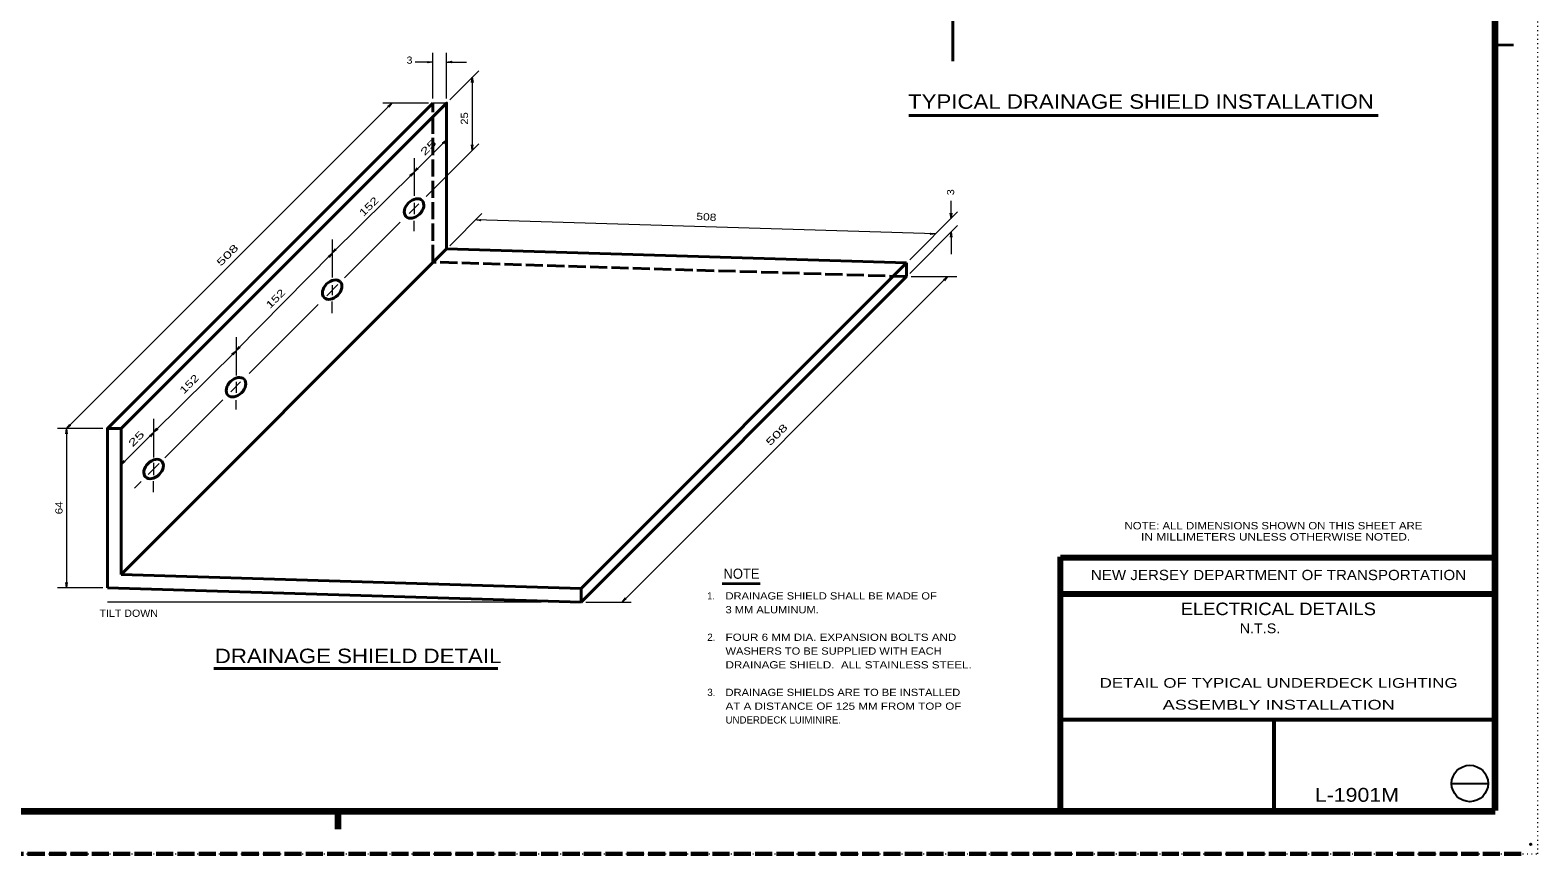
# Model space of a CAD drawing. Extents: x 312583 to 312854, y 144419 to 144597.
# Drawn here: x 312695 to 312853.5, y 144418.6 to 144505.2 of the extents above; entities that cross this region are included whole.
import ezdxf
from ezdxf.enums import TextEntityAlignment as Align

# ---------------------------------------------------------------- set-up
doc = ezdxf.new("R2010")
doc.units = 0
doc.header["$LTSCALE"] = 0.3
doc.header["$PDMODE"] = 32
doc.header["$PDSIZE"] = 0.15
doc.linetypes.add('DOTTED', pattern=[1.5, 0.3, -1.2])
doc.linetypes.add('LONG_DASHED', pattern=[7.5, 6, -1.5])
for name, color, linetype, lineweight in [('1', 7, 'Continuous', 40), ('10', 7, 'Continuous', 25), ('2', 7, 'Continuous', 13), ('62', 7, 'DOTTED', 13), ('63', 7, 'LONG_DASHED', 60)]:
    doc.layers.add(name, color=color, linetype=linetype, lineweight=lineweight)
doc.layers.add('39', color=7, linetype='Continuous')
doc.layers.add('5', color=7, linetype='Continuous')

msp = doc.modelspace()

# ---------------------------------------------------------------- linework, layer by layer
at = {"layer": '1', "lineweight": 158}
for p, q in [((312849, 144423.1446), (312849, 144585.0846)), ((312616.5, 144423.0846), (312849, 144423.0846)), ((312727.35, 144421.1646), (312727.35, 144423.0846))]:
    msp.add_line(p, q, dxfattribs=at)
at = {"layer": '1', "lineweight": 35}
msp.add_line((312849, 144503.6216), (312850.932, 144503.6216), dxfattribs=at)
at = {"layer": '1', "lineweight": 80}
for p, q in [((312803.31, 144423.1446), (312803.31, 144449.8146)), ((312803.31, 144449.7246), (312849, 144449.7246)), ((312803.31, 144445.9146), (312849, 144445.9146))]:
    msp.add_line(p, q, dxfattribs=at)
at = {"layer": '1', "lineweight": 53}
for p, q in [((312849, 144432.6666), (312803.092, 144432.6666)), ((312825.7547, 144432.6666), (312825.7547, 144423.1446))]:
    msp.add_line(p, q, dxfattribs=at)
at = {"layer": '10'}
msp.add_line((312844.4384, 144425.9659), (312848.2794, 144425.9659), dxfattribs=at)
msp.add_circle((312846.3494, 144425.9805), 1.9159, dxfattribs=at)
at = {"layer": '2', "lineweight": 40}
for p, q in [((312791.9754, 144501.9119), (312791.9754, 144578.5786)), ((312787.3711, 144496.1849), (312836.6956, 144496.1849)), ((312704.5283, 144447.9463), (312738.7523, 144482.1703)), ((312787.1213, 144480.6983), (312738.7523, 144482.1703)), ((312752.8973, 144446.4743), (312787.1213, 144480.6983)), ((312787.1213, 144480.6983), (312787.1213, 144479.2646)), ((312752.8973, 144445.0406), (312787.1213, 144479.2646)), ((312704.5283, 144463.2796), (312703.0946, 144463.2796)), ((312704.5283, 144447.9463), (312704.5283, 144463.2796)), ((312752.8973, 144445.0406), (312703.0946, 144446.5586)), ((312714.2947, 144438.0563), (312744.1415, 144438.0563))]:
    msp.add_line(p, q, dxfattribs=at)
at = {"layer": '2'}
for p, q in [((312737.3186, 144497.9789), (312737.3186, 144502.7706)), ((312738.7523, 144497.9789), (312738.7523, 144502.7706)), ((312737.3186, 144501.8123), (312735.4581, 144501.8123)), ((312738.7523, 144501.8123), (312740.853, 144501.8123)), ((312739.0896, 144497.8409), (312742.1333, 144500.8846)), ((312741.4586, 144500.2099), (312741.4586, 144492.5432)), ((312698.786, 144463.2796), (312733.01, 144497.5036)), ((312736.8433, 144497.5036), (312732.0516, 144497.5036)), ((312738.7523, 144497.5036), (312737.3186, 144497.5036)), ((312738.7523, 144493.6473), (312735.333, 144490.2512)), ((312742.1333, 144493.2179), (312736.5903, 144487.6749)), ((312735.333, 144491.6923), (312735.333, 144487.7439)), ((312735.333, 144490.2509), (312726.7233, 144481.7339)), ((312734.8116, 144485.8809), (312735.8313, 144486.9159)), ((312735.333, 144487.0233), (312735.333, 144485.8273)), ((312791.798, 144485.3749), (312791.798, 144487.2389)), ((312728.0343, 144479.1189), (312733.884, 144484.9686)), ((312735.333, 144484.0333), (312735.333, 144485.1066)), ((312739.0896, 144482.5076), (312742.4706, 144485.8886)), ((312790.165, 144483.7419), (312741.796, 144485.2139)), ((312787.4586, 144481.0356), (312792.4726, 144486.0496)), ((312787.4586, 144479.6019), (312792.4726, 144484.6159)), ((312726.7233, 144483.1669), (312726.7233, 144479.1726)), ((312791.798, 144483.9413), (312791.798, 144481.6336)), ((312726.7233, 144481.7256), (312716.611, 144471.4781)), ((312726.1713, 144477.2483), (312727.329, 144478.4213)), ((312726.7233, 144478.3599), (312726.7233, 144477.3173)), ((312757.2136, 144445.0406), (312791.4376, 144479.2646)), ((312787.6043, 144479.2646), (312792.396, 144479.2646)), ((312726.7233, 144475.4083), (312726.7233, 144476.6579)), ((312718.0063, 144469.0909), (312725.259, 144476.3436)), ((312716.611, 144472.9089), (312716.611, 144468.8686)), ((312716.611, 144471.4676), (312707.9476, 144462.874)), ((312716.0743, 144467.1436), (312717.1016, 144468.1863)), ((312716.611, 144468.1939), (312716.611, 144467.0286)), ((312709.1206, 144460.1976), (312715.231, 144466.3156)), ((312716.611, 144465.2729), (312716.611, 144466.2619)), ((312707.9476, 144464.3069), (312707.9476, 144460.2436)), ((312702.6193, 144463.2796), (312697.8276, 144463.2796)), ((312698.786, 144463.2796), (312698.786, 144446.5586)), ((312707.9476, 144462.8656), (312704.5283, 144459.4692)), ((312707.388, 144458.4726), (312708.5303, 144459.6073)), ((312707.9476, 144459.6839), (312707.9476, 144458.3729)), ((312705.939, 144457.0159), (312706.6443, 144457.7213)), ((312707.9476, 144456.5866), (312707.9476, 144457.7443)), ((312702.6193, 144446.5586), (312697.8276, 144446.5586)), ((312748.696, 144445.0406), (312703.0946, 144445.0406)), ((312753.3803, 144445.0406), (312758.172, 144445.0406))]:
    msp.add_line(p, q, dxfattribs=at)
at = {"layer": '2', "linetype": 'LONG_DASHED', "lineweight": 40}
for p, q in [((312737.3186, 144480.7826), (312737.3186, 144497.5036)), ((312787.1213, 144479.2646), (312737.3186, 144480.7826))]:
    msp.add_line(p, q, dxfattribs=at)
at = {"layer": '2', "lineweight": 35}
msp.add_line((312767.7342, 144446.9907), (312771.7367, 144446.9907), dxfattribs=at)
at = {"layer": '2'}
for points in [[(312736.7666, 144501.8813), (312737.3186, 144501.8123), (312736.7666, 144501.7356), (312736.8203, 144501.8123)], [(312739.3043, 144501.7433), (312738.7523, 144501.8123), (312739.3043, 144501.8889), (312739.2506, 144501.8123)], [(312741.3896, 144499.6579), (312741.4586, 144500.2099), (312741.5353, 144499.6579), (312741.4586, 144499.7116)], [(312732.573, 144497.1586), (312733.01, 144497.5036), (312732.6726, 144497.0589), (312732.6573, 144497.1509)], [(312738.3153, 144493.3099), (312738.7523, 144493.6473), (312738.415, 144493.2026), (312738.3996, 144493.2946)], [(312741.5276, 144493.0953), (312741.4586, 144492.5433), (312741.382, 144493.0953), (312741.4586, 144493.0416)], [(312734.896, 144489.9136), (312735.333, 144490.2509), (312734.9956, 144489.8063), (312734.9803, 144489.8983)], [(312735.77, 144490.5883), (312735.333, 144490.2509), (312735.6703, 144490.6956), (312735.6856, 144490.6036)], [(312742.348, 144485.1296), (312741.796, 144485.2139), (312742.348, 144485.2753), (312742.2943, 144485.1986)], [(312791.867, 144485.9269), (312791.798, 144485.3749), (312791.7213, 144485.9269), (312791.798, 144485.8733)], [(312789.613, 144483.8263), (312790.165, 144483.7419), (312789.613, 144483.6806), (312789.6666, 144483.7573)], [(312791.729, 144483.3893), (312791.798, 144483.9413), (312791.8746, 144483.3893), (312791.798, 144483.4429)], [(312726.2863, 144481.3806), (312726.7233, 144481.7256), (312726.3936, 144481.2809), (312726.3706, 144481.3729)], [(312727.1603, 144482.0629), (312726.7233, 144481.7256), (312727.0606, 144482.1703), (312727.076, 144482.0783)], [(312791.0006, 144478.9196), (312791.4376, 144479.2646), (312791.1003, 144478.8199), (312791.085, 144478.9119)], [(312717.048, 144471.8126), (312716.611, 144471.4676), (312716.9406, 144471.9123), (312716.9636, 144471.8203)], [(312716.174, 144471.1303), (312716.611, 144471.4676), (312716.2736, 144471.0229), (312716.2583, 144471.1149)], [(312698.717, 144462.7276), (312698.786, 144463.2796), (312698.8626, 144462.7276), (312698.786, 144462.7813)], [(312699.223, 144463.6246), (312698.786, 144463.2796), (312699.1233, 144463.7243), (312699.1386, 144463.6323)], [(312707.5106, 144462.5283), (312707.9476, 144462.8656), (312707.6103, 144462.4209), (312707.595, 144462.5129)], [(312708.3846, 144463.2029), (312707.9476, 144462.8656), (312708.285, 144463.3103), (312708.3003, 144463.2183)], [(312704.9653, 144459.8066), (312704.5283, 144459.4693), (312704.8656, 144459.9139), (312704.881, 144459.8219)], [(312698.855, 144447.1106), (312698.786, 144446.5586), (312698.7093, 144447.1106), (312698.786, 144447.0569)], [(312757.6506, 144445.3856), (312757.2136, 144445.0406), (312757.551, 144445.4853), (312757.5663, 144445.3933)]]:
    msp.add_lwpolyline(points, close=True, dxfattribs=at)
at = {"layer": '2', "lineweight": 40}
for points in [[(312703.0946, 144446.5586), (312703.0946, 144463.2796), (312737.3186, 144497.5036)], [(312738.7523, 144482.1703), (312738.7523, 144497.5036), (312704.5283, 144463.2796)], [(312752.8973, 144445.0406), (312752.8973, 144446.4743), (312704.5283, 144447.9463)]]:
    msp.add_lwpolyline(points, dxfattribs=at)
for centre in [(312735.333, 144486.4176), (312726.7233, 144477.8923), (312716.611, 144467.6343), (312707.9476, 144459.0323)]:
    msp.add_ellipse(centre, major_axis=(0.851, 0.8357), ratio=0.693667, dxfattribs=at)
at = {"layer": '39'}
msp.add_point((312852.75, 144419.5846), dxfattribs=at)
at = {"layer": '62'}
msp.add_lwpolyline([(312601.2, 144418.5846), (312853.5, 144418.5846), (312853.5, 144596.7846)], dxfattribs=at)
at = {"layer": '63'}
msp.add_line((312851.75, 144418.5846), (312583.526, 144418.5846), dxfattribs=at)

# ---------------------------------------------------------------- texts
at = {"layer": '1'}
for s, width, p in [('NOTE: ALL DIMENSIONS SHOWN ON THIS SHEET ARE', 1.15, (312810.0367, 144452.6872)), ('     IN MILLIMETERS UNLESS OTHERWISE NOTED.', 1.2, (312810.0366, 144451.5172))]:
    msp.add_text(s, height=0.78, dxfattribs=dict(at, width=width)).set_placement(p)
at = {"layer": '1', "width": 1.1}
for s, height, p in [('NEW JERSEY DEPARTMENT OF TRANSPORTATION', 1.08, (312826.2285, 144447.3546)), ('ELECTRICAL DETAILS', 1.315, (312826.2109, 144443.6759))]:
    msp.add_text(s, height=height, dxfattribs=at).set_placement(p, align=Align.CENTER)
at = {"layer": '2'}
for s, width, p in [('3 ', 1.1, (312734.5441, 144501.6301)), ('1.', 0.9, (312766.1702, 144445.3184)), ('DRAINAGE SHIELD SHALL BE MADE OF', 1.15, (312768.0868, 144445.3184)), ('TILT DOWN', 1.1, (312702.2581, 144443.495)), ('3 MM ALUMINUM.', 1.15, (312768.0868, 144443.8694)), ('FOUR 6 MM DIA. EXPANSION BOLTS AND', 1.2, (312768.0868, 144440.9714)), ('WASHERS TO BE SUPPLIED WITH EACH', 1.15, (312768.0868, 144439.5224)), ('DRAINAGE SHIELD.  ALL STAINLESS STEEL.', 1.2, (312768.0868, 144438.0734)), ('DRAINAGE SHIELDS ARE TO BE INSTALLED', 1.15, (312768.0868, 144435.1754)), ('AT A DISTANCE OF 125 MM FROM TOP OF', 1.2, (312768.0868, 144433.7264))]:
    msp.add_text(s, height=0.76, dxfattribs=dict(at, width=width)).set_placement(p)
for s, height, width, p in [('TYPICAL DRAINAGE SHIELD INSTALLATION', 1.52, 1.15, (312811.7625, 144496.8986)), ('NOTE', 1.07, 0.95, (312769.7628, 144447.4942)), ('    N.T.S.  ', 1.02, 1.1, (312823.87, 144441.778)), ('DRAINAGE SHIELD DETAIL', 1.52, 1.15, (312729.4511, 144438.6296)), ('    DETAIL OF TYPICAL UNDERDECK LIGHTING    ', 1.02, 1.3, (312826.2415, 144436.0399)), ('            ASSEMBLY INSTALLATION           ', 1.02, 1.4, (312825.9885, 144433.7476))]:
    msp.add_text(s, height=height, dxfattribs=dict(at, width=width)).set_placement(p, align=Align.CENTER)
for s, rotation, width, p in [('25 ', 90, 1.15, (312741.009, 144495.2321)), ('25', 45, 1.65, (312736.4386, 144491.9011)), ('3 ', 90, 1.1, (312792.1263, 144487.8135)), ('152', 45, 1.4, (312730.006, 144485.5129)), ('508 ', 356.514, 1.25, (312764.9924, 144485.2247)), ('508 ', 45, 1.6, (312715.0141, 144480.2941)), ('152', 45, 1.4, (312720.1909, 144475.8319)), ('152', 45, 1.4, (312711.1199, 144466.8602)), ('25', 45, 1.65, (312705.734, 144461.2928)), ('508 ', 45, 1.6, (312772.7711, 144461.412)), ('64 ', 90, 1.2, (312698.3728, 144454.2747))]:
    msp.add_text(s, height=0.76, rotation=rotation, dxfattribs=dict(at, width=width)).set_placement(p)
for s, p in [('2.', (312766.1702, 144440.9714)), ('3.', (312766.1702, 144435.1754)), ('UNDERDECK LUIMINIRE.', (312768.0868, 144432.2774))]:
    msp.add_text(s, height=0.76, dxfattribs=at).set_placement(p)
at = {"layer": '5', "width": 1.15}
msp.add_text('L-1901M  ', height=1.457, dxfattribs=at).set_placement((312835.0944, 144424.0569), align=Align.CENTER)

doc.saveas('drawing.dxf')
